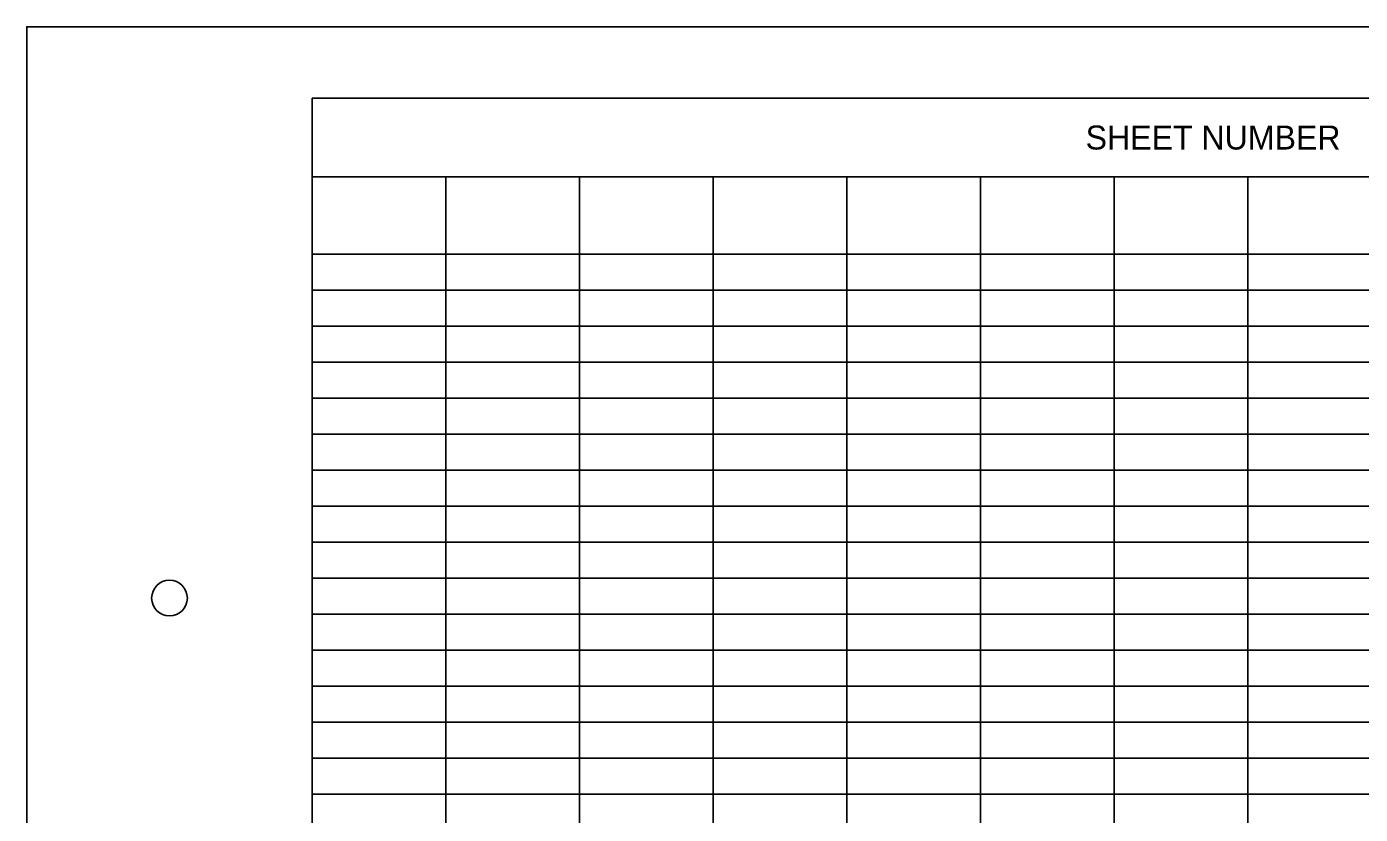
# Model space of a CAD drawing. Extents: x 1826847 to 2221677, y 500657 to 714743.
# Drawn here: x 1826846.6 to 1827313.6, y 714467.4 to 714743.1 of the extents above; entities that cross this region are included whole.
import ezdxf

# ---------------------------------------------------------------- set-up
doc = ezdxf.new("R2010")
doc.units = 0
for name, color, linetype in [('SH_Border', 7, 'Continuous'), ('SH_Cut_Line', 7, 'Continuous'), ('SH_Data', 7, 'Continuous'), ('SH_Text', 7, 'Continuous')]:
    doc.layers.add(name, color=color, linetype=linetype)

msp = doc.modelspace()

# ---------------------------------------------------------------- linework, layer by layer
at = {"layer": 'SH_Border'}
msp.add_lwpolyline([(1826946.62, 714718.08), (1828521.62, 714718.08), (1828521.62, 713668.08), (1826946.62, 713668.08)], close=True, dxfattribs=at)
msp.add_circle((1826896.62, 714543.08), 6.25, dxfattribs=at)
at = {"layer": 'SH_Cut_Line'}
msp.add_lwpolyline([(1826846.62, 713643.08), (1828546.62, 713643.08), (1828546.62, 714743.08), (1826846.62, 714743.08)], close=True, dxfattribs=at)
at = {"layer": 'SH_Data'}
for p, q in [((1826946.62, 714718.08), (1826993.42, 714718.08)), ((1826946.62, 714718.08), (1826946.62, 714663.48)), ((1826993.42, 714718.08), (1827040.22, 714718.08)), ((1827040.22, 714718.08), (1827087.02, 714718.08)), ((1827087.02, 714718.08), (1827133.82, 714718.08)), ((1827133.82, 714718.08), (1827180.62, 714718.08)), ((1827180.62, 714718.08), (1827227.42, 714718.08)), ((1827227.42, 714718.08), (1827274.22, 714718.08)), ((1827274.22, 714718.08), (1827321.02, 714718.08)), ((1826946.62, 714690.48), (1826993.42, 714690.48)), ((1826993.42, 714690.48), (1827040.22, 714690.48)), ((1826993.42, 714690.48), (1826993.42, 714663.48)), ((1827040.22, 714690.48), (1827087.02, 714690.48)), ((1827040.22, 714690.48), (1827040.22, 714663.48)), ((1827087.02, 714690.48), (1827133.82, 714690.48)), ((1827087.02, 714690.48), (1827087.02, 714663.48)), ((1827133.82, 714690.48), (1827180.62, 714690.48)), ((1827133.82, 714690.48), (1827133.82, 714663.48)), ((1827180.62, 714690.48), (1827227.42, 714690.48)), ((1827180.62, 714690.48), (1827180.62, 714663.48)), ((1827227.42, 714690.48), (1827274.22, 714690.48)), ((1827227.42, 714690.48), (1827227.42, 714663.48)), ((1827274.22, 714690.48), (1827321.02, 714690.48)), ((1827274.22, 714690.48), (1827274.22, 714663.48)), ((1826946.62, 714663.48), (1826993.42, 714663.48)), ((1826946.62, 714663.48), (1826946.62, 714600.48)), ((1826993.42, 714663.48), (1827040.22, 714663.48)), ((1826993.42, 714663.48), (1826993.42, 714600.48)), ((1827040.22, 714663.48), (1827087.02, 714663.48)), ((1827040.22, 714663.48), (1827040.22, 714600.48)), ((1827087.02, 714663.48), (1827133.82, 714663.48)), ((1827087.02, 714663.48), (1827087.02, 714600.48)), ((1827133.82, 714663.48), (1827180.62, 714663.48)), ((1827133.82, 714663.48), (1827133.82, 714600.48)), ((1827180.62, 714663.48), (1827227.42, 714663.48)), ((1827180.62, 714663.48), (1827180.62, 714600.48)), ((1827227.42, 714663.48), (1827274.22, 714663.48)), ((1827227.42, 714663.48), (1827227.42, 714600.48)), ((1827274.22, 714663.48), (1827321.02, 714663.48)), ((1827274.22, 714663.48), (1827274.22, 714600.48)), ((1826946.62, 714650.88), (1826993.42, 714650.88)), ((1826993.42, 714650.88), (1827040.22, 714650.88)), ((1827040.22, 714650.88), (1827087.02, 714650.88)), ((1827087.02, 714650.88), (1827133.82, 714650.88)), ((1827133.82, 714650.88), (1827180.62, 714650.88)), ((1827180.62, 714650.88), (1827227.42, 714650.88)), ((1827227.42, 714650.88), (1827274.22, 714650.88)), ((1827274.22, 714650.88), (1827321.02, 714650.88)), ((1826946.62, 714638.28), (1826993.42, 714638.28)), ((1826993.42, 714638.28), (1827040.22, 714638.28)), ((1827040.22, 714638.28), (1827087.02, 714638.28)), ((1827087.02, 714638.28), (1827133.82, 714638.28)), ((1827133.82, 714638.28), (1827180.62, 714638.28)), ((1827180.62, 714638.28), (1827227.42, 714638.28)), ((1827227.42, 714638.28), (1827274.22, 714638.28)), ((1827274.22, 714638.28), (1827321.02, 714638.28)), ((1826946.62, 714625.68), (1826993.42, 714625.68)), ((1826993.42, 714625.68), (1827040.22, 714625.68)), ((1827040.22, 714625.68), (1827087.02, 714625.68)), ((1827087.02, 714625.68), (1827133.82, 714625.68)), ((1827133.82, 714625.68), (1827180.62, 714625.68)), ((1827180.62, 714625.68), (1827227.42, 714625.68)), ((1827227.42, 714625.68), (1827274.22, 714625.68)), ((1827274.22, 714625.68), (1827321.02, 714625.68)), ((1826946.62, 714613.08), (1826993.42, 714613.08)), ((1826993.42, 714613.08), (1827040.22, 714613.08)), ((1827040.22, 714613.08), (1827087.02, 714613.08)), ((1827087.02, 714613.08), (1827133.82, 714613.08)), ((1827133.82, 714613.08), (1827180.62, 714613.08)), ((1827180.62, 714613.08), (1827227.42, 714613.08)), ((1827227.42, 714613.08), (1827274.22, 714613.08)), ((1827274.22, 714613.08), (1827321.02, 714613.08)), ((1826946.62, 714600.48), (1826993.42, 714600.48)), ((1826946.62, 714600.48), (1826946.62, 714587.88)), ((1826993.42, 714600.48), (1827040.22, 714600.48)), ((1826993.42, 714600.48), (1826993.42, 714587.88)), ((1827040.22, 714600.48), (1827087.02, 714600.48)), ((1827040.22, 714600.48), (1827040.22, 714587.88)), ((1827087.02, 714600.48), (1827133.82, 714600.48)), ((1827087.02, 714600.48), (1827087.02, 714587.88)), ((1827133.82, 714600.48), (1827180.62, 714600.48)), ((1827133.82, 714600.48), (1827133.82, 714587.88)), ((1827180.62, 714600.48), (1827227.42, 714600.48)), ((1827180.62, 714600.48), (1827180.62, 714587.88)), ((1827227.42, 714600.48), (1827274.22, 714600.48)), ((1827227.42, 714600.48), (1827227.42, 714587.88)), ((1827274.22, 714600.48), (1827321.02, 714600.48)), ((1827274.22, 714600.48), (1827274.22, 714587.88)), ((1826946.62, 714587.88), (1826993.42, 714587.88)), ((1826946.62, 714587.88), (1826946.62, 714575.28)), ((1826993.42, 714587.88), (1827040.22, 714587.88)), ((1826993.42, 714587.88), (1826993.42, 714575.28)), ((1827040.22, 714587.88), (1827087.02, 714587.88)), ((1827040.22, 714587.88), (1827040.22, 714575.28)), ((1827087.02, 714587.88), (1827133.82, 714587.88)), ((1827087.02, 714587.88), (1827087.02, 714575.28)), ((1827133.82, 714587.88), (1827180.62, 714587.88)), ((1827133.82, 714587.88), (1827133.82, 714575.28)), ((1827180.62, 714587.88), (1827227.42, 714587.88)), ((1827180.62, 714587.88), (1827180.62, 714575.28)), ((1827227.42, 714587.88), (1827274.22, 714587.88)), ((1827227.42, 714587.88), (1827227.42, 714575.28)), ((1827274.22, 714587.88), (1827321.02, 714587.88)), ((1827274.22, 714587.88), (1827274.22, 714575.28)), ((1826946.62, 714575.28), (1826993.42, 714575.28)), ((1826946.62, 714575.28), (1826946.62, 714562.68)), ((1826993.42, 714575.28), (1827040.22, 714575.28)), ((1826993.42, 714575.28), (1826993.42, 714562.68)), ((1827040.22, 714575.28), (1827087.02, 714575.28)), ((1827040.22, 714575.28), (1827040.22, 714562.68)), ((1827087.02, 714575.28), (1827133.82, 714575.28)), ((1827087.02, 714575.28), (1827087.02, 714562.68)), ((1827133.82, 714575.28), (1827180.62, 714575.28)), ((1827133.82, 714575.28), (1827133.82, 714562.68)), ((1827180.62, 714575.28), (1827227.42, 714575.28)), ((1827180.62, 714575.28), (1827180.62, 714562.68)), ((1827227.42, 714575.28), (1827274.22, 714575.28)), ((1827227.42, 714575.28), (1827227.42, 714562.68)), ((1827274.22, 714575.28), (1827321.02, 714575.28)), ((1827274.22, 714575.28), (1827274.22, 714562.68)), ((1826946.62, 714562.68), (1826993.42, 714562.68)), ((1826946.62, 714562.68), (1826946.62, 714550.08)), ((1826993.42, 714562.68), (1827040.22, 714562.68)), ((1826993.42, 714562.68), (1826993.42, 714550.08)), ((1827040.22, 714562.68), (1827087.02, 714562.68)), ((1827040.22, 714562.68), (1827040.22, 714550.08)), ((1827087.02, 714562.68), (1827133.82, 714562.68)), ((1827087.02, 714562.68), (1827087.02, 714550.08)), ((1827133.82, 714562.68), (1827180.62, 714562.68)), ((1827133.82, 714562.68), (1827133.82, 714550.08)), ((1827180.62, 714562.68), (1827227.42, 714562.68)), ((1827180.62, 714562.68), (1827180.62, 714550.08)), ((1827227.42, 714562.68), (1827274.22, 714562.68)), ((1827227.42, 714562.68), (1827227.42, 714550.08)), ((1827274.22, 714562.68), (1827321.02, 714562.68)), ((1827274.22, 714562.68), (1827274.22, 714550.08)), ((1826946.62, 714550.08), (1826993.42, 714550.08)), ((1826946.62, 714550.08), (1826946.62, 714537.48)), ((1826993.42, 714550.08), (1827040.22, 714550.08)), ((1826993.42, 714550.08), (1826993.42, 714537.48)), ((1827040.22, 714550.08), (1827087.02, 714550.08)), ((1827040.22, 714550.08), (1827040.22, 714537.48)), ((1827087.02, 714550.08), (1827133.82, 714550.08)), ((1827087.02, 714550.08), (1827087.02, 714537.48)), ((1827133.82, 714550.08), (1827180.62, 714550.08)), ((1827133.82, 714550.08), (1827133.82, 714537.48)), ((1827180.62, 714550.08), (1827227.42, 714550.08)), ((1827180.62, 714550.08), (1827180.62, 714537.48)), ((1827227.42, 714550.08), (1827274.22, 714550.08)), ((1827227.42, 714550.08), (1827227.42, 714537.48)), ((1827274.22, 714550.08), (1827321.02, 714550.08)), ((1827274.22, 714550.08), (1827274.22, 714537.48)), ((1826946.62, 714537.48), (1826993.42, 714537.48)), ((1826946.62, 714537.48), (1826946.62, 714524.88)), ((1826993.42, 714537.48), (1827040.22, 714537.48)), ((1826993.42, 714537.48), (1826993.42, 714524.88)), ((1827040.22, 714537.48), (1827087.02, 714537.48)), ((1827040.22, 714537.48), (1827040.22, 714524.88)), ((1827087.02, 714537.48), (1827133.82, 714537.48)), ((1827087.02, 714537.48), (1827087.02, 714524.88)), ((1827133.82, 714537.48), (1827180.62, 714537.48)), ((1827133.82, 714537.48), (1827133.82, 714524.88)), ((1827180.62, 714537.48), (1827227.42, 714537.48)), ((1827180.62, 714537.48), (1827180.62, 714524.88)), ((1827227.42, 714537.48), (1827274.22, 714537.48)), ((1827227.42, 714537.48), (1827227.42, 714524.88)), ((1827274.22, 714537.48), (1827321.02, 714537.48)), ((1827274.22, 714537.48), (1827274.22, 714524.88)), ((1826946.62, 714524.88), (1826993.42, 714524.88)), ((1826946.62, 714524.88), (1826946.62, 714512.28)), ((1826993.42, 714524.88), (1827040.22, 714524.88)), ((1826993.42, 714524.88), (1826993.42, 714512.28)), ((1827040.22, 714524.88), (1827087.02, 714524.88)), ((1827040.22, 714524.88), (1827040.22, 714512.28)), ((1827087.02, 714524.88), (1827133.82, 714524.88)), ((1827087.02, 714524.88), (1827087.02, 714512.28)), ((1827133.82, 714524.88), (1827180.62, 714524.88)), ((1827133.82, 714524.88), (1827133.82, 714512.28)), ((1827180.62, 714524.88), (1827227.42, 714524.88)), ((1827180.62, 714524.88), (1827180.62, 714512.28)), ((1827227.42, 714524.88), (1827274.22, 714524.88)), ((1827227.42, 714524.88), (1827227.42, 714512.28)), ((1827274.22, 714524.88), (1827321.02, 714524.88)), ((1827274.22, 714524.88), (1827274.22, 714512.28)), ((1826946.62, 714512.28), (1826993.42, 714512.28)), ((1826946.62, 714512.28), (1826946.62, 714499.68)), ((1826993.42, 714512.28), (1827040.22, 714512.28)), ((1826993.42, 714512.28), (1826993.42, 714499.68)), ((1827040.22, 714512.28), (1827087.02, 714512.28)), ((1827040.22, 714512.28), (1827040.22, 714499.68)), ((1827087.02, 714512.28), (1827133.82, 714512.28)), ((1827087.02, 714512.28), (1827087.02, 714499.68)), ((1827133.82, 714512.28), (1827180.62, 714512.28)), ((1827133.82, 714512.28), (1827133.82, 714499.68)), ((1827180.62, 714512.28), (1827227.42, 714512.28)), ((1827180.62, 714512.28), (1827180.62, 714499.68)), ((1827227.42, 714512.28), (1827274.22, 714512.28)), ((1827227.42, 714512.28), (1827227.42, 714499.68)), ((1827274.22, 714512.28), (1827321.02, 714512.28)), ((1827274.22, 714512.28), (1827274.22, 714499.68)), ((1826946.62, 714499.68), (1826993.42, 714499.68)), ((1826946.62, 714499.68), (1826946.62, 714487.08)), ((1826993.42, 714499.68), (1827040.22, 714499.68)), ((1826993.42, 714499.68), (1826993.42, 714487.08)), ((1827040.22, 714499.68), (1827087.02, 714499.68)), ((1827040.22, 714499.68), (1827040.22, 714487.08)), ((1827087.02, 714499.68), (1827133.82, 714499.68)), ((1827087.02, 714499.68), (1827087.02, 714487.08)), ((1827133.82, 714499.68), (1827180.62, 714499.68)), ((1827133.82, 714499.68), (1827133.82, 714487.08)), ((1827180.62, 714499.68), (1827227.42, 714499.68)), ((1827180.62, 714499.68), (1827180.62, 714487.08)), ((1827227.42, 714499.68), (1827274.22, 714499.68)), ((1827227.42, 714499.68), (1827227.42, 714487.08)), ((1827274.22, 714499.68), (1827321.02, 714499.68)), ((1827274.22, 714499.68), (1827274.22, 714487.08)), ((1826946.62, 714487.08), (1826993.42, 714487.08)), ((1826946.62, 714487.08), (1826946.62, 714474.48)), ((1826993.42, 714487.08), (1827040.22, 714487.08)), ((1826993.42, 714487.08), (1826993.42, 714474.48)), ((1827040.22, 714487.08), (1827087.02, 714487.08)), ((1827040.22, 714487.08), (1827040.22, 714474.48)), ((1827087.02, 714487.08), (1827133.82, 714487.08)), ((1827087.02, 714487.08), (1827087.02, 714474.48)), ((1827133.82, 714487.08), (1827180.62, 714487.08)), ((1827133.82, 714487.08), (1827133.82, 714474.48)), ((1827180.62, 714487.08), (1827227.42, 714487.08)), ((1827180.62, 714487.08), (1827180.62, 714474.48)), ((1827227.42, 714487.08), (1827274.22, 714487.08)), ((1827227.42, 714487.08), (1827227.42, 714474.48)), ((1827274.22, 714487.08), (1827321.02, 714487.08)), ((1827274.22, 714487.08), (1827274.22, 714474.48)), ((1826946.62, 714474.48), (1826993.42, 714474.48)), ((1826946.62, 714474.48), (1826946.62, 714461.88)), ((1826993.42, 714474.48), (1827040.22, 714474.48)), ((1826993.42, 714474.48), (1826993.42, 714461.88)), ((1827040.22, 714474.48), (1827087.02, 714474.48)), ((1827040.22, 714474.48), (1827040.22, 714461.88)), ((1827087.02, 714474.48), (1827133.82, 714474.48)), ((1827087.02, 714474.48), (1827087.02, 714461.88)), ((1827133.82, 714474.48), (1827180.62, 714474.48)), ((1827133.82, 714474.48), (1827133.82, 714461.88)), ((1827180.62, 714474.48), (1827227.42, 714474.48)), ((1827180.62, 714474.48), (1827180.62, 714461.88)), ((1827227.42, 714474.48), (1827274.22, 714474.48)), ((1827227.42, 714474.48), (1827227.42, 714461.88)), ((1827274.22, 714474.48), (1827321.02, 714474.48)), ((1827274.22, 714474.48), (1827274.22, 714461.88))]:
    msp.add_line(p, q, dxfattribs=at)

# ---------------------------------------------------------------- texts
at = {"layer": 'SH_Text'}
msp.add_text('SHEET NUMBER', height=8.4, dxfattribs=at).set_placement((1827217.37, 714700.08))

doc.saveas('drawing.dxf')
